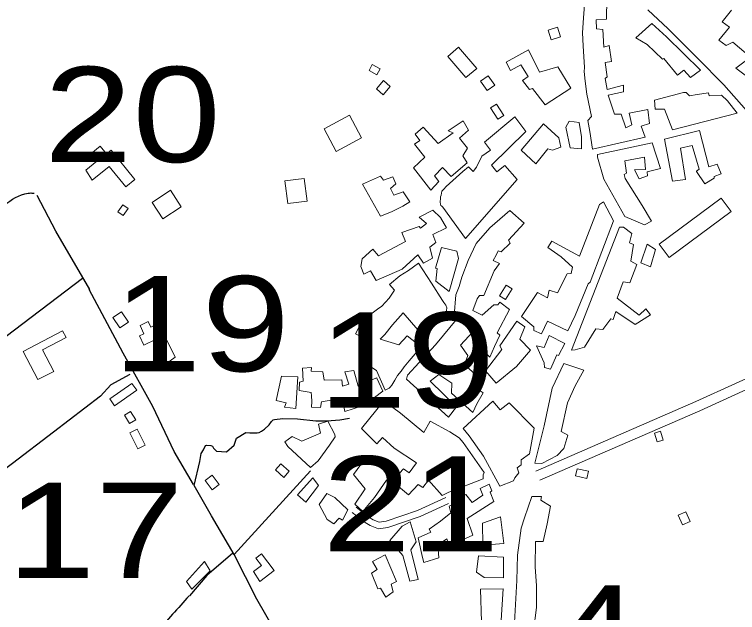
# Model space of a CAD drawing. Extents: x 476989 to 498418, y 4381813 to 4416555.
# Drawn here: x 485864.6 to 486244.3, y 4385962.5 to 4386276.6 of the extents above; entities that cross this region are included whole.
import ezdxf
from ezdxf.enums import TextEntityAlignment as Align

# ---------------------------------------------------------------- set-up
doc = ezdxf.new("R2010")
doc.units = 0
doc.header["$LTSCALE"] = 20
doc.linetypes.add('MEDIUM_DASHED', pattern=[4.5, 3, -1.5])
for name, color, linetype, lineweight in [('13', 7, 'Continuous', 13), ('37', 7, 'Continuous', 13), ('38', 7, 'Continuous', 13), ('47', 7, 'Continuous', 13), ('48', 7, 'MEDIUM_DASHED', 13), ('6', 7, 'Continuous', 25)]:
    doc.layers.add(name, color=color, linetype=linetype, lineweight=lineweight)

msp = doc.modelspace()

# ---------------------------------------------------------------- linework, layer by layer
at = {"layer": '37'}
for points in [[(486140.46, 4386031.99), (486224.53, 4386068.46), (486308.29, 4386106.74), (486373.95, 4386135.42), (486418.71, 4386154.45)], [(486138.39, 4386036.78), (486222.41, 4386073.23), (486284.84, 4386101.74)]]:
    msp.add_lwpolyline(points, dxfattribs=at)
at = {"layer": '38'}
for points in [[(486092.45, 4386019.76), (486077.52, 4386012.9), (486060.59, 4386007.07), (486055.64, 4386006.48), (486051.37, 4386008.12), (486048.75, 4386009.68), (486041.87, 4386015.08)], [(486091.02, 4386022.87), (486076.24, 4386016.08), (486059.82, 4386010.43), (486056.08, 4386009.98), (486052.87, 4386011.21), (486050.69, 4386012.51), (486043.98, 4386017.77)]]:
    msp.add_lwpolyline(points, dxfattribs=at)
at = {"layer": '47'}
for points in [[(486175.7, 4386284.88), (486175.47, 4386274.15), (486170.06, 4386273.78), (486170.22, 4386268.98), (486173.51, 4386268.63), (486174.06, 4386259.47), (486176.92, 4386260.32), (486178, 4386251.91), (486174.77, 4386251.35), (486175.79, 4386243.91), (486174.8, 4386242.95), (486175.76, 4386237.16), (486184.43, 4386239.43), (486184.3, 4386235.91), (486176.25, 4386234.22), (486179.63, 4386224.19), (486183.08, 4386224.14), (486185.53, 4386217.06), (486188.7, 4386218.66), (486187.37, 4386224.68), (486197.22, 4386226.64), (486198.02, 4386219.35), (486193.72, 4386217.91), (486195.74, 4386212.18), (486168.04, 4386205.9), (486166.67, 4386215.15), (486165.7, 4386220.94), (486167.61, 4386223.02), (486165.07, 4386234.76), (486164.27, 4386241.52), (486163.67, 4386246.63), (486163.85, 4386248.81), (486163.26, 4386260.15), (486162.83, 4386266.98), (486163.32, 4386274.85), (486164.31, 4386286.47)], [(486248.92, 4386226.2), (486237.1, 4386239.58), (486223.27, 4386253.58), (486207.89, 4386269.11), (486197.22, 4386278.94)], [(486241.12, 4386278.91), (486236.15, 4386272.68), (486240.09, 4386269.85), (486234.44, 4386263.1), (486238.22, 4386260.2), (486241.78, 4386262.1), (486251.04, 4386254.16), (486243.31, 4386248.42), (486249.69, 4386243.67)]]:
    msp.add_lwpolyline(points, dxfattribs=at)
for points in [[(486224.83, 4386247.33), (486206.92, 4386264.77), (486199.22, 4386271.79), (486190.86, 4386264.25), (486196.74, 4386260.87), (486204.8, 4386253.02), (486205.49, 4386253.46), (486212.71, 4386244.73), (486216.13, 4386247.31), (486219.6, 4386243.51)], [(486101.64, 4386243.39), (486092.09, 4386254.5), (486097.74, 4386259.36), (486107.29, 4386248.25)], [(486156.79, 4386237.8), (486143.31, 4386229.14), (486136.6, 4386237.64), (486135.1, 4386237.21), (486131.26, 4386241.84), (486134.29, 4386244.05), (486130.55, 4386250.18), (486125.11, 4386247.19), (486122.84, 4386251.5), (486134.57, 4386257.93), (486140.33, 4386246.22), (486149.9, 4386249.08)], [(486050.75, 4386247.13), (486054.91, 4386244.85), (486056.61, 4386247.94), (486052.45, 4386250.22)], [(486113.36, 4386244.43), (486116.87, 4386239.41), (486112.8, 4386236.56), (486109.29, 4386241.58)], [(486058.32, 4386241.84), (486054.61, 4386237.51), (486058.22, 4386234.41), (486061.93, 4386238.74)], [(486244.09, 4386224.77), (486210.05, 4386216.03), (486205.86, 4386226.82), (486200.98, 4386226.81), (486200.6, 4386231.62), (486215.88, 4386235.53), (486217.31, 4386235.51), (486219.01, 4386233.76), (486223.07, 4386234.53), (486229.09, 4386235.49), (486229.29, 4386233.91), (486235.9, 4386234.12), (486239.01, 4386231.22)], [(486114.62, 4386227.6), (486118.44, 4386221.54), (486121.47, 4386223.45), (486117.65, 4386229.51)], [(486040.43, 4386223.64), (486027.16, 4386216.6), (486033.48, 4386204.68), (486046.75, 4386211.72)], [(486083.16, 4386184.23), (486074.1, 4386195.99), (486080.04, 4386201.68), (486074.58, 4386208.44), (486077.38, 4386210.43), (486075.03, 4386213.76), (486079.21, 4386217.38), (486087.12, 4386208.86), (486094.93, 4386214.45), (486092.24, 4386215.54), (486100.27, 4386220.68), (486102.97, 4386215.84), (486098.34, 4386211.63), (486102.54, 4386206.31), (486100, 4386202.37), (486102.28, 4386198.59), (486093.85, 4386191.43), (486089.34, 4386196.22), (486085.22, 4386191.86), (486087.43, 4386188.82)], [(486127.24, 4386222.84), (486111.36, 4386209.56), (486114.53, 4386205.39), (486109.98, 4386202.08), (486107.12, 4386196.34), (486105.44, 4386194.12), (486103, 4386196.63), (486100.04, 4386194.04), (486091.29, 4386186.14), (486090, 4386184.81), (486089.24, 4386183.99), (486089.01, 4386183.77), (486088.68, 4386181.75), (486088.37, 4386180.78), (486088.21, 4386180.18), (486088.18, 4386178.01), (486088.24, 4386177.03), (486088.53, 4386176.28), (486088.97, 4386175.82), (486089.56, 4386175.36), (486101.41, 4386158.98), (486128.57, 4386189.96), (486122.07, 4386197.33), (486117.82, 4386194.01), (486115.02, 4386197.43), (486133.13, 4386215.11)], [(486162.26, 4386206.06), (486162.35, 4386212.29), (486161.18, 4386219.81), (486155.87, 4386220.48), (486154.09, 4386217.36), (486156.34, 4386206.59)], [(486142.34, 4386219.1), (486130.59, 4386205.31), (486138.36, 4386198.07), (486144.7, 4386205.94), (486147.17, 4386205.37), (486151.47, 4386206.81), (486150.41, 4386211.71)], [(486205.93, 4386211.14), (486210.19, 4386189.09), (486216.96, 4386189.82), (486214.27, 4386206.36), (486220.44, 4386207.7), (486224.16, 4386195.34), (486222.8, 4386194.31), (486222.8, 4386194.16), (486222.8, 4386194.16), (486227.13, 4386187.57), (486231.97, 4386190.65), (486231.91, 4386191.48), (486235.61, 4386192.93), (486233.58, 4386197.98), (486229.28, 4386196.54), (486224.23, 4386215.6)], [(486199.45, 4386209.13), (486170.77, 4386203.09), (486170.75, 4386201.59), (486174.04, 4386190.06), (486185.01, 4386170.39), (486195.38, 4386166.04), (486199.16, 4386168.09), (486194.1, 4386176.26), (486185.3, 4386190.42), (486184.73, 4386192.46), (486185.94, 4386193.19), (486185.13, 4386199.65), (486195.44, 4386201.61), (486195.87, 4386195.22), (486190.17, 4386194.93), (486192.65, 4386190.32), (486196.95, 4386191.83), (486196.75, 4386193.93), (486203.76, 4386195.63)], [(485905.4, 4386189.48), (485914.36, 4386196.78), (485923.06, 4386186.09), (485927.81, 4386189.97), (485915.26, 4386205.32), (485912.85, 4386203.36), (485909.58, 4386207.37), (485904.67, 4386203.37), (485907.77, 4386199.55), (485902.01, 4386194.88)], [(486016.77, 4386190.51), (486018.29, 4386178.58), (486008.1, 4386177.28), (486006.58, 4386189.21)], [(486047.34, 4386187.52), (486056.78, 4386170.65), (486062.52, 4386172.9), (486068.56, 4386175.81), (486072.12, 4386178.24), (486068.67, 4386183.46), (486063.84, 4386181.66), (486062.02, 4386185.14), (486064.83, 4386187.57), (486063.23, 4386191.27), (486058.33, 4386189.47), (486056.7, 4386191.59)], [(485946.45, 4386184.24), (485936.81, 4386177.9), (485942.48, 4386169.29), (485952.12, 4386175.63)], [(486235.65, 4386180.17), (486203.17, 4386155.93), (486208.42, 4386148.89), (486240.9, 4386173.13)], [(485921.43, 4386176.57), (485918.89, 4386172.89), (485921.72, 4386170.94), (485924.26, 4386174.62)], [(486179.13, 4386168.22), (486166.89, 4386135.91), (486165.82, 4386135.1), (486159.06, 4386118.54), (486155.19, 4386110.34), (486144.46, 4386115.45), (486141.36, 4386108.81), (486137.33, 4386110.67), (486137.29, 4386112.47), (486130.84, 4386117.89), (486139.27, 4386130.53), (486144.48, 4386127.75), (486145.37, 4386131.86), (486149.7, 4386130.3), (486154.87, 4386140.28), (486156.97, 4386140.55), (486157.54, 4386143.85), (486151.62, 4386149.26), (486144.71, 4386154.16), (486146.78, 4386157.43), (486161.31, 4386149.72), (486171.82, 4386176.81), (486173.94, 4386178.13)], [(486091.43, 4386164.45), (486084.33, 4386161.1), (486085.92, 4386156.73), (486082.73, 4386154.3), (486084.08, 4386148.5), (486079.31, 4386146.02), (486076.37, 4386150.34), (486068.16, 4386142.88), (486054.42, 4386136.92), (486051.49, 4386141.99), (486047.94, 4386140.24), (486046.42, 4386144.16), (486047.16, 4386148.28), (486052.78, 4386153.3), (486055.73, 4386149.88), (486069.95, 4386157.33), (486067.99, 4386162.01), (486077.04, 4386165.19), (486077.78, 4386164.42), (486080.96, 4386166.85), (486077.03, 4386170.14), (486084.29, 4386173.79), (486088.36, 4386169.9)], [(486124.66, 4386173.66), (486114.17, 4386164.43), (486107.07, 4386156.28), (486102.89, 4386147.33), (486099.54, 4386138.6), (486098.05, 4386133.74), (486096.26, 4386129.27), (486095.5, 4386118.47), (486097.36, 4386117.32), (486085.6, 4386103.08), (486077.14, 4386093.82), (486070.97, 4386087.16), (486070.49, 4386084.99), (486092.49, 4386065.02), (486096.62, 4386070.43), (486082.78, 4386083.91), (486087.33, 4386087.45), (486094.24, 4386082.85), (486094.09, 4386077.75), (486105.35, 4386067.61), (486107.37, 4386072.16), (486110.68, 4386077.89), (486109.12, 4386078.88), (486109.98, 4386081.65), (486105.71, 4386087.04), (486105.21, 4386088.77), (486100.91, 4386092.73), (486102.63, 4386097.44), (486098.73, 4386102.82), (486105.36, 4386110.08), (486106.82, 4386112.16), (486110.6, 4386109.4), (486106.03, 4386104.52), (486110.25, 4386100.4), (486114.25, 4386096.67), (486116.65, 4386102.11), (486119.36, 4386108.08), (486118.11, 4386109.29), (486124.51, 4386121.66), (486119.46, 4386125.41), (486118.47, 4386124), (486116.29, 4386124.1), (486110.21, 4386118.71), (486105.29, 4386121.03), (486107.56, 4386127.3), (486108.78, 4386128.94), (486111.03, 4386128.91), (486116.55, 4386141.96), (486119.23, 4386145.82), (486116.02, 4386147.29), (486117.49, 4386150.12), (486118.57, 4386152.36), (486120.22, 4386151.89), (486124.93, 4386156.47), (486123.91, 4386158.06), (486132.14, 4386166.95)], [(486182.31, 4386164.88), (486157.14, 4386100.18), (486159.02, 4386100.45), (486163.96, 4386101.84), (486169.8, 4386111.53), (486173.54, 4386111.2), (486177.65, 4386116.79), (486178.94, 4386116.36), (486180.3, 4386120.52), (486190.52, 4386113.79), (486198.57, 4386118.74), (486196.19, 4386122.04), (486192.57, 4386118.68), (486181.05, 4386127.64), (486184.25, 4386136.11), (486187.63, 4386135.57), (486191.33, 4386145.25), (486188.3, 4386146.95), (486189.57, 4386155.69), (486187.49, 4386156.7), (486188.73, 4386161.53), (486184.32, 4386164.93)], [(486092.76, 4386131.12), (486097.66, 4386148.46), (486096.89, 4386152.29), (486088.87, 4386154.11), (486085.72, 4386143.39), (486086.45, 4386143.16), (486085.85, 4386136.44)], [(486201.12, 4386153.13), (486196.89, 4386155.89), (486193.52, 4386146.18), (486198.59, 4386144.08)], [(486043.66, 4386108.79), (486046.83, 4386114.89), (486049.11, 4386117.19), (486055.26, 4386121.83), (486057.45, 4386123.3), (486061.34, 4386127.52), (486064.1, 4386131.75), (486061.59, 4386134.79), (486066.99, 4386139.22), (486071.45, 4386142.08), (486076.76, 4386145.98), (486083.52, 4386135.53), (486089.31, 4386126.37), (486089.97, 4386125.38), (486091.15, 4386123.86), (486091.66, 4386122.51), (486091.49, 4386121.16), (486090.86, 4386119.21), (486088.43, 4386117.15), (486086.13, 4386114.03), (486081.88, 4386110.41), (486079.66, 4386107.07), (486068.66, 4386119.91), (486063.02, 4386113.54), (486058.97, 4386108.57), (486056.68, 4386106.05), (486066.39, 4386102.98), (486070.74, 4386107.87), (486078.08, 4386102.06), (486071.9, 4386094.72), (486069.15, 4386091.46), (486067.62, 4386089.23), (486065.71, 4386086.94), (486064.33, 4386084.55), (486062.79, 4386081.95), (486061.8, 4386080.76), (486061.26, 4386080.32), (486059.22, 4386079.22), (486054.64, 4386089.57), (486048.99, 4386093.33), (486046.78, 4386095.54), (486046.25, 4386100.57), (486048.8, 4386106.16)], [(486122.82, 4386134.36), (486119.35, 4386128.88), (486122.41, 4386126.94), (486125.88, 4386132.42)], [(485916.3, 4386117.37), (485919.95, 4386111.96), (485924.45, 4386115), (485920.8, 4386120.41)], [(485948.87, 4386096.56), (485940.19, 4386114.32), (485936.24, 4386112.4), (485934.85, 4386115.25), (485930.52, 4386113.14), (485932.58, 4386108.89), (485930.18, 4386107.74), (485932.51, 4386102.87), (485938.97, 4386105.96), (485943.28, 4386096.92), (485939.83, 4386095.3), (485941.71, 4386091.28)], [(486135.53, 4386100.19), (486128.28, 4386091.74), (486117.5, 4386082.97), (486111.89, 4386089.35), (486120.46, 4386100.63), (486119.51, 4386102.52), (486128.4, 4386115.53), (486132.63, 4386112.54), (486129.91, 4386105.97)], [(485876.89, 4386084.84), (485869.15, 4386099.58), (485889.8, 4386110.43), (485891.63, 4386106.92), (485879.31, 4386100.5), (485885.28, 4386089.02)], [(486153.52, 4386103.76), (486145.4, 4386107.93), (486142.68, 4386101.74), (486138.65, 4386102.62), (486142.64, 4386093.56), (486142.98, 4386091.23), (486146.12, 4386090.21), (486149.38, 4386097.74), (486150.2, 4386097.5)], [(486152.99, 4386093.26), (486146.88, 4386080.22), (486142.77, 4386060.54), (486137.84, 4386040.88), (486141.51, 4386040.75), (486149.53, 4386044.99), (486153.1, 4386048.54), (486155.15, 4386055.56), (486151.58, 4386057.49), (486155.02, 4386072.52), (486158.98, 4386081.47), (486163.6, 4386089.73)], [(486057.94, 4386078.72), (486053.69, 4386075.48), (486048.99, 4386071.94), (486046.72, 4386070.77), (486038.05, 4386067.97), (486036.65, 4386075.12), (486025.75, 4386073.18), (486025.33, 4386070.11), (486020.53, 4386070.25), (486020.72, 4386073.32), (486020.54, 4386076.25), (486020.41, 4386078.05), (486014.05, 4386079.05), (486014.19, 4386083.47), (486016.15, 4386083.97), (486015.87, 4386090.88), (486020.53, 4386091.18), (486020.42, 4386089.16), (486026.57, 4386088.92), (486027.11, 4386084.56), (486036.41, 4386084.65), (486036.74, 4386081.42), (486040.06, 4386082.35), (486037.98, 4386088.91), (486042.79, 4386089.59), (486045.07, 4386081.3), (486050.36, 4386083.93), (486054.89, 4386085.66), (486054.89, 4386085.59)], [(486013.4, 4386086.18), (486012.34, 4386069.69), (486006.34, 4386070.3), (486007.28, 4386072.69), (486001.97, 4386073.89), (486004.85, 4386086.68)], [(485914.56, 4386074.62), (485926.22, 4386082.81), (485928.74, 4386079.22), (485917.08, 4386071.03)], [(486071.42, 4386024.2), (486076.52, 4386029.75), (486078.97, 4386028.07), (486082.03, 4386032), (486089.2, 4386023.94), (486092.6, 4386025.77), (486110.71, 4386032.71), (486110.74, 4386034.74), (486111.13, 4386036.08), (486100.25, 4386051.85), (486098.11, 4386054.2), (486093.13, 4386057.35), (486082.93, 4386062.98), (486079.54, 4386057.1), (486067.31, 4386067.25), (486058.54, 4386073.61), (486046.78, 4386059.07), (486054.77, 4386051.07), (486057.89, 4386054.41), (486064.04, 4386048.84), (486075.71, 4386041.09), (486071.81, 4386035.75), (486068.84, 4386037.97), (486062.89, 4386031.45)], [(486119.36, 4386028.84), (486110.95, 4386044.57), (486103.3, 4386055.26), (486100.13, 4386059.05), (486115.72, 4386073.54), (486119.7, 4386068.98), (486124.26, 4386072.66), (486137.5, 4386059.27), (486134.98, 4386045.8), (486130.73, 4386042.71), (486130.7, 4386040.08), (486128.57, 4386038.54), (486129.36, 4386035.75), (486127.3, 4386033.15), (486126.67, 4386031.66)], [(485922.4, 4386066.1), (485925.03, 4386061.71), (485928.21, 4386063.62), (485925.58, 4386068.01)], [(486020.07, 4386038.59), (486008.15, 4386049.72), (486006.53, 4386052.07), (486010.33, 4386054.94), (486015.54, 4386052.46), (486025.21, 4386056.6), (486024.23, 4386061.42), (486029.2, 4386063), (486032.85, 4386055.89), (486032.91, 4386054.69), (486029.92, 4386050.31), (486024.03, 4386042.21)], [(485928.97, 4386058.73), (485933.14, 4386050.42), (485929.35, 4386048.52), (485925.18, 4386056.83)], [(486205.24, 4386053.04), (486203.76, 4386057.64), (486200.64, 4386056.64), (486202.12, 4386052.04)], [(486043.28, 4386019.35), (486048.65, 4386027.38), (486042.53, 4386035.04), (486048.96, 4386043.58), (486051.39, 4386040.54), (486055.78, 4386043.41), (486062.86, 4386034.23), (486061.24, 4386031.62), (486059.97, 4386032.02), (486053.61, 4386022.95), (486047.58, 4386015.54)], [(486008.87, 4386036.73), (486005.96, 4386033.46), (486001.6, 4386037.35), (486004.51, 4386040.62)], [(485964.67, 4386031.73), (485968.36, 4386026.94), (485972, 4386029.75), (485968.31, 4386034.54)], [(486160.08, 4386038.01), (486166.02, 4386036.69), (486165.18, 4386032.91), (486159.24, 4386034.23)], [(486024.29, 4386029.23), (486017.56, 4386020.39), (486013.19, 4386024.28), (486021.27, 4386033.25)], [(486079.46, 4385988.74), (486078.9, 4385991.3), (486076.57, 4386001.69), (486083.14, 4386004.75), (486082.34, 4386006.26), (486088.25, 4386010.38), (486093.72, 4386014.87), (486092.79, 4386018.41), (486096.79, 4386020.01), (486096.37, 4386021.66), (486101.58, 4386024.37), (486104.9, 4386020.27), (486110.43, 4386024.09), (486109.06, 4386027.56), (486113.82, 4386029.89), (486115.27, 4386026.35), (486114.28, 4386025.76), (486116.31, 4386020.85), (486102.23, 4386011.83), (486105.26, 4386003.15), (486098.68, 4386000.17), (486092.8, 4385997.85), (486091.57, 4386001.1), (486086.87, 4385997.86), (486087.45, 4385991.25)], [(486039.64, 4386016.4), (486032.75, 4386022.95), (486028.51, 4386025.04), (486024.6, 4386019.17), (486028.76, 4386011.3), (486032.25, 4386009), (486035.07, 4386012.04), (486036.79, 4386011.04)], [(486126.74, 4385941.77), (486127.18, 4385957.29), (486128.4, 4385979.26), (486128.74, 4385992.54), (486130.59, 4386006.69), (486132.4, 4386012.14), (486136.31, 4386023.42), (486141.41, 4386023.42), (486140.94, 4386021.55), (486146.07, 4386018.4), (486144.28, 4386009.05), (486142.12, 4385999.7), (486138.15, 4385999.83), (486137.96, 4385986.4), (486138.64, 4385976.56), (486138.63, 4385965.08), (486137.1, 4385952.8), (486135.29, 4385952.45), (486134.48, 4385942.93)], [(486121.62, 4385998.72), (486119.72, 4386012.7), (486110.3, 4386009.38), (486110.43, 4385997.9)], [(486213.16, 4386013.69), (486215.44, 4386008.51), (486219.34, 4386010.22), (486217.06, 4386015.4)], [(486061.69, 4386000.33), (486068.56, 4385992.5), (486072.19, 4385978.94), (486076.63, 4385979.78), (486072.65, 4385995.37), (486075.49, 4385999.6), (486072.42, 4386010.15), (486068.18, 4386007.89)], [(485993.33, 4385978.8), (486000.92, 4385984.54), (485994.33, 4385993.24), (485991.34, 4385990.99), (485994.22, 4385987.15), (485990.1, 4385984.07)], [(486065.14, 4385978.74), (486059.26, 4385992.71), (486052.61, 4385989.35), (486055.1, 4385985.04), (486051.99, 4385983.06), (486055.33, 4385974.83), (486056.83, 4385975.26), (486059.54, 4385970.57), (486063.41, 4385973.36), (486062.42, 4385977.43)], [(485927.68, 4385990.02), (485929.81, 4385986.26), (485926.02, 4385984.11), (485923.89, 4385987.87)], [(485957.78, 4385974.73), (485967.3, 4385984.35), (485964.37, 4385989.34), (485954.84, 4385978.75)], [(486121.3, 4385991.59), (486121.37, 4385980.64), (486111.24, 4385980.93), (486107.15, 4385983.69), (486108.25, 4385992.3)], [(486121.21, 4385974.86), (486120.15, 4385958.52), (486109.86, 4385957.61), (486109.27, 4385974.66)]]:
    msp.add_lwpolyline(points, close=True, dxfattribs=at)
at = {"layer": '48'}
msp.add_lwpolyline([(486151.32, 4386264.82), (486146.44, 4386263.29), (486144.85, 4386268.36), (486149.73, 4386269.89)], close=True, dxfattribs=at)
at = {"layer": '6'}
msp.add_line((485979.85, 4385992.89), (486019.99, 4386036.92), dxfattribs=at)
for points in [[(485904.09, 4386132.12), (485886.31, 4386162.77), (485876.46, 4386181.58)], [(485900.27, 4386137.97), (485855.62, 4386104.09), (485839.67, 4386091.4)], [(485958.59, 4386029.72), (485948.44, 4386046.98), (485937.24, 4386070.62), (485921.71, 4386098.64), (485903.77, 4386132.16)], [(485925.15, 4386087.47), (485915.18, 4386082.02), (485909.67, 4386076.07), (485885.14, 4386057.23), (485863.44, 4386040.74), (485859.35, 4386037.6)], [(485958.85, 4386029.11), (485961.86, 4386041.77), (485962.6, 4386045.96), (485963.85, 4386047.9), (485964.48, 4386049.42), (485964.97, 4386050.23), (485965.54, 4386050.43), (485967.74, 4386050.19), (485968.58, 4386049.81), (485969.13, 4386048.77), (485970.73, 4386047.3), (485975.98, 4386046.89), (485979.96, 4386050.42), (485981.22, 4386054.04), (485986.1, 4386057.1), (485988.09, 4386056.91), (485990.5, 4386056.79), (485992.09, 4386056.87), (485993.09, 4386057.1), (485994.37, 4386057.65), (485995.8, 4386058.76), (485998.37, 4386061.09), (485999.48, 4386062.83), (486000.42, 4386063.6), (486001.11, 4386063.91), (486005.43, 4386064.38), (486013.27, 4386064.27), (486022.9, 4386063.08), (486028.51, 4386063.23), (486035.45, 4386063.67), (486040.55, 4386064.6)], [(486039.35, 4385887.02), (486034.01, 4385895.17), (486023.27, 4385913.43), (486015.17, 4385928.47), (486006.09, 4385944.75), (485991.82, 4385969.4), (485979.85, 4385992.89), (485968.11, 4386013.21), (485958.85, 4386029.11)], [(485979.18, 4385993.65), (485965.62, 4385981.93), (485956.45, 4385971.26)]]:
    msp.add_lwpolyline(points, dxfattribs=at)
for points in [[(485618.34, 4385970.59), (485618.38, 4385973.67), (485619.29, 4385979.81), (485620.52, 4385981.96), (485624.55, 4385985.66), (485631.1, 4385992.24), (485636.66, 4385997.79), (485642.54, 4386005.21), (485653.19, 4386020.51), (485656.61, 4386023.69), (485660.14, 4386028.67), (485662.93, 4386034.86), (485676.75, 4386051.92), (485681.6, 4386054.92), (485684.85, 4386056.53), (485691.33, 4386058.54), (485700.94, 4386059.07), (485703.19, 4386059.12), (485707.58, 4386061.46), (485738.19, 4386081.95), (485766.12, 4386104.21), (485805.91, 4386132.23), (485848.56, 4386165.68), (485871.76, 4386182.68), (485874.39, 4386182.72), (485874.99, 4386182.56)], [(485956.23, 4385971.26), (485947.54, 4385961.52), (485930.31, 4385942.56), (485916.08, 4385928.8), (485905.26, 4385917.55), (485892.78, 4385905.28), (485874.27, 4385886.03), (485833.81, 4385845.65), (485813.14, 4385823.32), (485781.72, 4385801.83), (485774.07, 4385789.96), (485761.33, 4385781.76), (485746.04, 4385772.43)]]:
    msp.add_spline(points, degree=3, dxfattribs=at)

# ---------------------------------------------------------------- texts
at = {"layer": '13', "width": 1.25}
for s, p in [('20', (485926.47, 4386199.05)), ('19', (485962.75, 4386089.17)), ('19', (486070.61, 4386070.15)), ('21', (486072.73, 4385994.53)), ('17', (485907, 4385980.59)), ('4', (486169.71, 4385926.78))]:
    msp.add_text(s, height=50, dxfattribs=at).set_placement(p, align=Align.CENTER)

doc.saveas('drawing.dxf')
